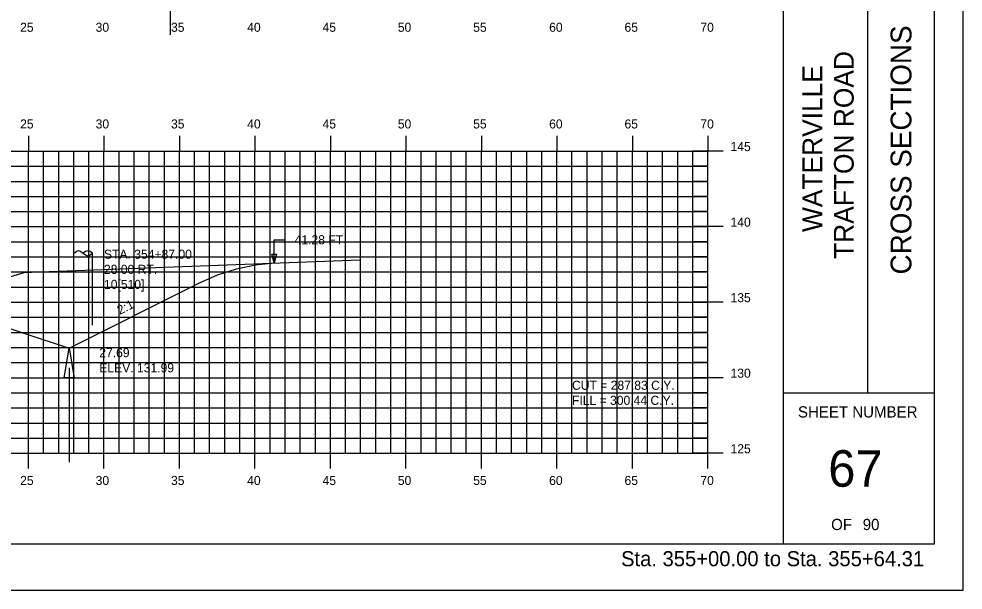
# Model space of a CAD drawing. Extents: x 1145416 to 1145586, y 608981 to 609091.
# Drawn here: x 1145523.3 to 1145585.8, y 608981.3 to 609019.1 of the extents above; entities that cross this region are included whole.
import ezdxf

# ---------------------------------------------------------------- set-up
doc = ezdxf.new("R2010")
doc.units = 0
for name, color, linetype in [('ANNOTATION', 7, 'Continuous'), ('BORDER', 7, 'Continuous'), ('D_Drainage_Ditch_Line', 7, 'Continuous'), ('D_Roadway_SlopeLines', 7, 'Continuous'), ('D_Roadway_SubGrade', 7, 'Continuous'), ('D_Text_Standard', 7, 'Continuous'), ('D_Utilities_Pole_Joint_Rt', 7, 'Continuous'), ('H_V ANNOTATION', 7, 'Continuous'), ('HIGHWAY_TITLE', 7, 'Continuous'), ('MAJOR', 7, 'Continuous'), ('MINOR', 7, 'Continuous'), ('PLOT BOUNDARY', 7, 'Continuous'), ('S_Roadway_Centerline', 7, 'Continuous')]:
    doc.layers.add(name, color=color, linetype=linetype)

msp = doc.modelspace()

# ---------------------------------------------------------------- linework, layer by layer
msp.add_lwpolyline([(1145459.897, 609002.864), (1145461.147, 609002.721), (1145462.397, 609002.44), (1145463.647, 609002.022), (1145464.897, 609001.465), (1145473.164, 608997.332), (1145476.164, 608998.332), (1145483.888, 609000.906), (1145483.889, 609000.906), (1145487.889, 609001.066), (1145498.889, 609001.286), (1145509.889, 609001.066), (1145515.987, 609000.823), (1145523.577, 608998.293), (1145526.577, 608997.293), (1145535.165, 609001.587), (1145536.415, 609002.14), (1145537.665, 609002.548), (1145538.915, 609002.812), (1145540.165, 609002.931)])
at = {"layer": 'BORDER'}
for p, q in [((1145573.889, 608984.335), (1145573.889, 609089.335)), ((1145579.48, 608994.338), (1145579.48, 609029.338)), ((1145573.889, 608994.338), (1145583.889, 608994.338))]:
    msp.add_line(p, q, dxfattribs=at)
msp.add_lwpolyline([(1145423.889, 608984.335), (1145583.889, 608984.335), (1145583.889, 609089.335), (1145423.889, 609089.335)], close=True, dxfattribs=at)
at = {"layer": 'D_Drainage_Ditch_Line'}
for p, q in [((1145533.264, 609024.275), (1145533.263, 609018.032)), ((1145526.577, 608995.98), (1145526.576, 608989.737))]:
    msp.add_line(p, q, dxfattribs=at)
msp.add_lwpolyline([(1145526.905, 608995.324), (1145526.249, 608995.324), (1145526.577, 608997.293)], close=True, dxfattribs=at)
at = {"layer": 'D_Roadway_SlopeLines'}
for points in [[(1145526.577, 608997.293), (1145535.165, 609001.587), (1145536.415, 609002.14), (1145537.665, 609002.548), (1145538.915, 609002.812), (1145540.165, 609002.931)], [(1145523.577, 608998.293), (1145526.577, 608997.293)]]:
    msp.add_lwpolyline(points, dxfattribs=at)
at = {"layer": 'D_Roadway_SubGrade'}
msp.add_lwpolyline([(1145509.889, 609000.65), (1145509.889, 609000.816), (1145515.987, 609000.573), (1145515.987, 609000.823), (1145515.987, 609000.823), (1145523.577, 608998.293), (1145509.889, 608998.566)], close=True, dxfattribs=at)
at = {"layer": 'D_Text_Standard'}
msp.add_lwpolyline([(1145540.165, 609002.931), (1145540.159, 609004.468), (1145540.839, 609004.468)], dxfattribs=at)
msp.add_lwpolyline([(1145540.165, 609002.931), (1145540.017, 609003.513), (1145540.308, 609003.514)], close=True, dxfattribs=at)
at = {"layer": 'D_Utilities_Pole_Joint_Rt'}
for p, q in [((1145526.889, 609003.571), (1145527.045, 609003.682)), ((1145526.889, 608998.814), (1145526.889, 609003.571)), ((1145527.357, 609003.682), (1145527.513, 609003.571)), ((1145527.669, 609003.682), (1145527.513, 609003.571)), ((1145527.513, 609003.571), (1145527.669, 609003.461)), ((1145528.139, 609003.571), (1145527.982, 609003.682)), ((1145527.982, 609003.461), (1145528.139, 609003.571)), ((1145528.139, 608998.814), (1145528.139, 609003.571))]:
    msp.add_line(p, q, dxfattribs=at)
for centre, start, end in [((1145527.201, 609003.461), 90, 125.26439), ((1145527.201, 609003.461), 54.73561, 90), ((1145527.826, 609003.461), 90, 125.26439), ((1145527.826, 609003.682), 234.73561, 270), ((1145527.826, 609003.461), 54.73561, 90), ((1145527.826, 609003.682), 270, 305.26439)]:
    msp.add_arc(centre, 0.271, start, end, dxfattribs=at)
at = {"layer": 'MAJOR'}
for p, q in [((1145523.889, 609011.337), (1145523.889, 609010.335)), ((1145528.889, 609011.337), (1145528.889, 609010.335)), ((1145533.889, 609011.337), (1145533.889, 609010.335)), ((1145538.889, 609011.337), (1145538.889, 609010.335)), ((1145543.889, 609011.337), (1145543.889, 609010.335)), ((1145548.889, 609011.337), (1145548.889, 609010.335)), ((1145553.889, 609011.337), (1145553.889, 609010.335)), ((1145558.889, 609011.337), (1145558.889, 609010.335)), ((1145563.889, 609011.337), (1145563.889, 609010.335)), ((1145568.889, 609011.337), (1145568.889, 609010.335)), ((1145428.889, 609010.335), (1145568.889, 609010.335)), ((1145428.889, 609010.335), (1145568.889, 609010.335)), ((1145523.889, 608990.335), (1145523.889, 609010.335)), ((1145528.889, 608990.335), (1145528.889, 609010.335)), ((1145533.889, 608990.335), (1145533.889, 609010.335)), ((1145538.889, 608990.335), (1145538.889, 609010.335)), ((1145543.889, 608990.335), (1145543.889, 609010.335)), ((1145548.889, 608990.335), (1145548.889, 609010.335)), ((1145553.889, 608990.335), (1145553.889, 609010.335)), ((1145558.889, 608990.335), (1145558.889, 609010.335)), ((1145563.889, 608990.335), (1145563.889, 609010.335)), ((1145569.891, 609010.335), (1145567.887, 609010.335)), ((1145568.889, 608990.335), (1145568.889, 609010.335)), ((1145568.889, 608990.335), (1145568.889, 609010.335)), ((1145428.889, 609005.335), (1145568.889, 609005.335)), ((1145569.891, 609005.335), (1145567.887, 609005.335)), ((1145428.889, 609000.335), (1145568.889, 609000.335)), ((1145569.891, 609000.335), (1145567.887, 609000.335)), ((1145428.889, 608995.335), (1145568.889, 608995.335)), ((1145569.891, 608995.335), (1145567.887, 608995.335)), ((1145428.889, 608990.335), (1145568.889, 608990.335)), ((1145428.889, 608990.335), (1145568.889, 608990.335)), ((1145523.889, 608989.333), (1145523.889, 608990.335)), ((1145528.889, 608989.333), (1145528.889, 608990.335)), ((1145533.889, 608989.333), (1145533.889, 608990.335)), ((1145538.889, 608989.333), (1145538.889, 608990.335)), ((1145543.889, 608989.333), (1145543.889, 608990.335)), ((1145548.889, 608989.333), (1145548.889, 608990.335)), ((1145553.889, 608989.333), (1145553.889, 608990.335)), ((1145558.889, 608989.333), (1145558.889, 608990.335)), ((1145563.889, 608989.333), (1145563.889, 608990.335)), ((1145569.891, 608990.335), (1145567.887, 608990.335)), ((1145568.889, 608989.333), (1145568.889, 608990.335))]:
    msp.add_line(p, q, dxfattribs=at)
at = {"layer": 'MINOR'}
for p, q in [((1145524.889, 608990.335), (1145524.889, 609010.335)), ((1145525.889, 608990.335), (1145525.889, 609010.335)), ((1145526.889, 608990.335), (1145526.889, 609010.335)), ((1145527.889, 608990.335), (1145527.889, 609010.335)), ((1145529.889, 608990.335), (1145529.889, 609010.335)), ((1145530.889, 608990.335), (1145530.889, 609010.335)), ((1145531.889, 608990.335), (1145531.889, 609010.335)), ((1145532.889, 608990.335), (1145532.889, 609010.335)), ((1145534.889, 608990.335), (1145534.889, 609010.335)), ((1145535.889, 608990.335), (1145535.889, 609010.335)), ((1145536.889, 608990.335), (1145536.889, 609010.335)), ((1145537.889, 608990.335), (1145537.889, 609010.335)), ((1145539.889, 608990.335), (1145539.889, 609010.335)), ((1145540.889, 608990.335), (1145540.889, 609010.335)), ((1145541.889, 608990.335), (1145541.889, 609010.335)), ((1145542.889, 608990.335), (1145542.889, 609010.335)), ((1145544.889, 608990.335), (1145544.889, 609010.335)), ((1145545.889, 608990.335), (1145545.889, 609010.335)), ((1145546.889, 608990.335), (1145546.889, 609010.335)), ((1145547.889, 608990.335), (1145547.889, 609010.335)), ((1145549.889, 608990.335), (1145549.889, 609010.335)), ((1145550.889, 608990.335), (1145550.889, 609010.335)), ((1145551.889, 608990.335), (1145551.889, 609010.335)), ((1145552.889, 608990.335), (1145552.889, 609010.335)), ((1145554.889, 608990.335), (1145554.889, 609010.335)), ((1145555.889, 608990.335), (1145555.889, 609010.335)), ((1145556.889, 608990.335), (1145556.889, 609010.335)), ((1145557.889, 608990.335), (1145557.889, 609010.335)), ((1145559.889, 608990.335), (1145559.889, 609010.335)), ((1145560.889, 608990.335), (1145560.889, 609010.335)), ((1145561.889, 608990.335), (1145561.889, 609010.335)), ((1145562.889, 608990.335), (1145562.889, 609010.335)), ((1145564.889, 608990.335), (1145564.889, 609010.335)), ((1145565.889, 608990.335), (1145565.889, 609010.335)), ((1145566.889, 608990.335), (1145566.889, 609010.335)), ((1145567.889, 608990.335), (1145567.889, 609010.335)), ((1145428.889, 609009.335), (1145568.889, 609009.335)), ((1145568.889, 609009.335), (1145567.887, 609009.335)), ((1145428.889, 609008.335), (1145568.889, 609008.335)), ((1145568.889, 609008.335), (1145567.887, 609008.335)), ((1145428.889, 609007.335), (1145568.889, 609007.335)), ((1145568.889, 609007.335), (1145567.887, 609007.335)), ((1145428.889, 609006.335), (1145568.889, 609006.335)), ((1145568.889, 609006.335), (1145567.887, 609006.335)), ((1145428.889, 609004.335), (1145568.889, 609004.335)), ((1145568.889, 609004.335), (1145567.887, 609004.335)), ((1145428.889, 609003.335), (1145568.889, 609003.335)), ((1145568.889, 609003.335), (1145567.887, 609003.335)), ((1145428.889, 609002.335), (1145568.889, 609002.335)), ((1145568.889, 609002.335), (1145567.887, 609002.335)), ((1145428.889, 609001.335), (1145568.889, 609001.335)), ((1145568.889, 609001.335), (1145567.887, 609001.335)), ((1145428.889, 608999.335), (1145568.889, 608999.335)), ((1145568.889, 608999.335), (1145567.887, 608999.335)), ((1145428.889, 608998.335), (1145568.889, 608998.335)), ((1145568.889, 608998.335), (1145567.887, 608998.335)), ((1145428.889, 608997.335), (1145568.889, 608997.335)), ((1145568.889, 608997.335), (1145567.887, 608997.335)), ((1145428.889, 608996.335), (1145568.889, 608996.335)), ((1145568.889, 608996.335), (1145567.887, 608996.335)), ((1145428.889, 608994.335), (1145568.889, 608994.335)), ((1145568.889, 608994.335), (1145567.887, 608994.335)), ((1145428.889, 608993.335), (1145568.889, 608993.335)), ((1145568.889, 608993.335), (1145567.887, 608993.335)), ((1145428.889, 608992.335), (1145568.889, 608992.335)), ((1145568.889, 608992.335), (1145567.887, 608992.335)), ((1145428.889, 608991.335), (1145568.889, 608991.335)), ((1145568.889, 608991.335), (1145567.887, 608991.335))]:
    msp.add_line(p, q, dxfattribs=at)
at = {"layer": 'PLOT BOUNDARY'}
msp.add_lwpolyline([(1145415.795, 608981.276), (1145585.795, 608981.276), (1145585.795, 609091.276), (1145415.795, 609091.276)], close=True, dxfattribs=at)
at = {"layer": 'S_Roadway_Centerline'}
msp.add_lwpolyline([(1145440.356, 609003.793), (1145453.175, 609003.264), (1145465.44, 609002.534), (1145473.538, 609000.489), (1145477.984, 608999.152), (1145480.44, 608999.716), (1145482.168, 609000.197), (1145484.192, 609000.33), (1145484.829, 609000.367), (1145486.595, 609000.386), (1145495.634, 609000.566), (1145497.444, 609000.542), (1145506.677, 609000.41), (1145507.295, 609000.357), (1145510.974, 609000.051), (1145513.492, 608999.566), (1145513.977, 608999.427), (1145517.137, 609000.366), (1145523.601, 609002.296), (1145524.098, 609002.327), (1145545.847, 609003.145)], dxfattribs=at)

# ---------------------------------------------------------------- texts
at = {"layer": 'ANNOTATION'}
msp.add_text('2:1', height=0.6, rotation=26.56505, dxfattribs=at).set_placement((1145529.944, 608999.494))
at = {"layer": 'BORDER'}
msp.add_text('CROSS SECTIONS', height=1.37787, rotation=90, dxfattribs=at).set_placement((1145582.373, 609002.172))
for s, height, p in [('SHEET NUMBER', 0.74527, (1145574.854, 608992.701)), ('67', 2.4194, (1145576.864, 608988.118)), ('OF', 0.7453, (1145577.056, 608985.248)), ('90', 0.7453, (1145579.145, 608985.248))]:
    msp.add_text(s, height=height, dxfattribs=at).set_placement(p)
at = {"layer": 'D_Text_Standard'}
for s, p in [('41.28 FT', (1145541.519, 609004.168)), ('STA. 354+87.00', (1145528.889, 609003.212)), ('28.00 RT.', (1145528.889, 609002.21)), ('10[510] ', (1145528.889, 609001.214)), ('27.69', (1145528.577, 608996.693)), ('ELEV. 131.99', (1145528.577, 608995.691)), ('CUT = 287.83 C.Y.', (1145559.889, 608994.535)), ('FILL = 300.44 C.Y.', (1145559.889, 608993.539))]:
    msp.add_text(s, height=0.6, dxfattribs=at).set_placement(p)
at = {"layer": 'H_V ANNOTATION'}
for s, height, p in [('25', 0.6, (1145523.335, 609018.235)), ('30', 0.6, (1145528.337, 609018.235)), ('35', 0.6, (1145533.329, 609018.235)), ('40', 0.6, (1145538.375, 609018.235)), ('45', 0.6, (1145543.367, 609018.235)), ('50', 0.6, (1145548.353, 609018.235)), ('55', 0.6, (1145553.345, 609018.235)), ('60', 0.6, (1145558.375, 609018.235)), ('65', 0.6, (1145563.367, 609018.235)), ('70', 0.6, (1145568.391, 609018.235)), ('25', 0.6, (1145523.335, 609011.835)), ('30', 0.6, (1145528.337, 609011.835)), ('35', 0.6, (1145533.329, 609011.835)), ('40', 0.6, (1145538.375, 609011.835)), ('45', 0.6, (1145543.367, 609011.835)), ('50', 0.6, (1145548.353, 609011.835)), ('55', 0.6, (1145553.345, 609011.835)), ('60', 0.6, (1145558.375, 609011.835)), ('65', 0.6, (1145563.367, 609011.835)), ('70', 0.6, (1145568.391, 609011.835)), ('145', 0.6, (1145570.389, 609010.335)), ('140', 0.6, (1145570.389, 609005.335)), ('135', 0.6, (1145570.389, 609000.335)), ('130', 0.6, (1145570.389, 608995.335)), ('125', 0.6, (1145570.389, 608990.335)), ('25', 0.6, (1145523.335, 608988.235)), ('30', 0.6, (1145528.337, 608988.235)), ('35', 0.6, (1145533.329, 608988.235)), ('40', 0.6, (1145538.375, 608988.235)), ('45', 0.6, (1145543.367, 608988.235)), ('50', 0.6, (1145548.353, 608988.235)), ('55', 0.6, (1145553.345, 608988.235)), ('60', 0.6, (1145558.375, 608988.235)), ('65', 0.6, (1145563.367, 608988.235)), ('70', 0.6, (1145568.391, 608988.235)), ('Sta. 355+00.00 to Sta. 355+64.31', 1.0002, (1145563.137, 608982.855))]:
    msp.add_text(s, height=height, dxfattribs=at).set_placement(p)
at = {"layer": 'HIGHWAY_TITLE'}
for s, height, p in [('TRAFTON ROAD', 1.30428, (1145578.548, 609003.201)), ('WATERVILLE', 1.3043, (1145576.461, 609004.98))]:
    msp.add_text(s, height=height, rotation=90, dxfattribs=at).set_placement(p)

doc.saveas('drawing.dxf')
